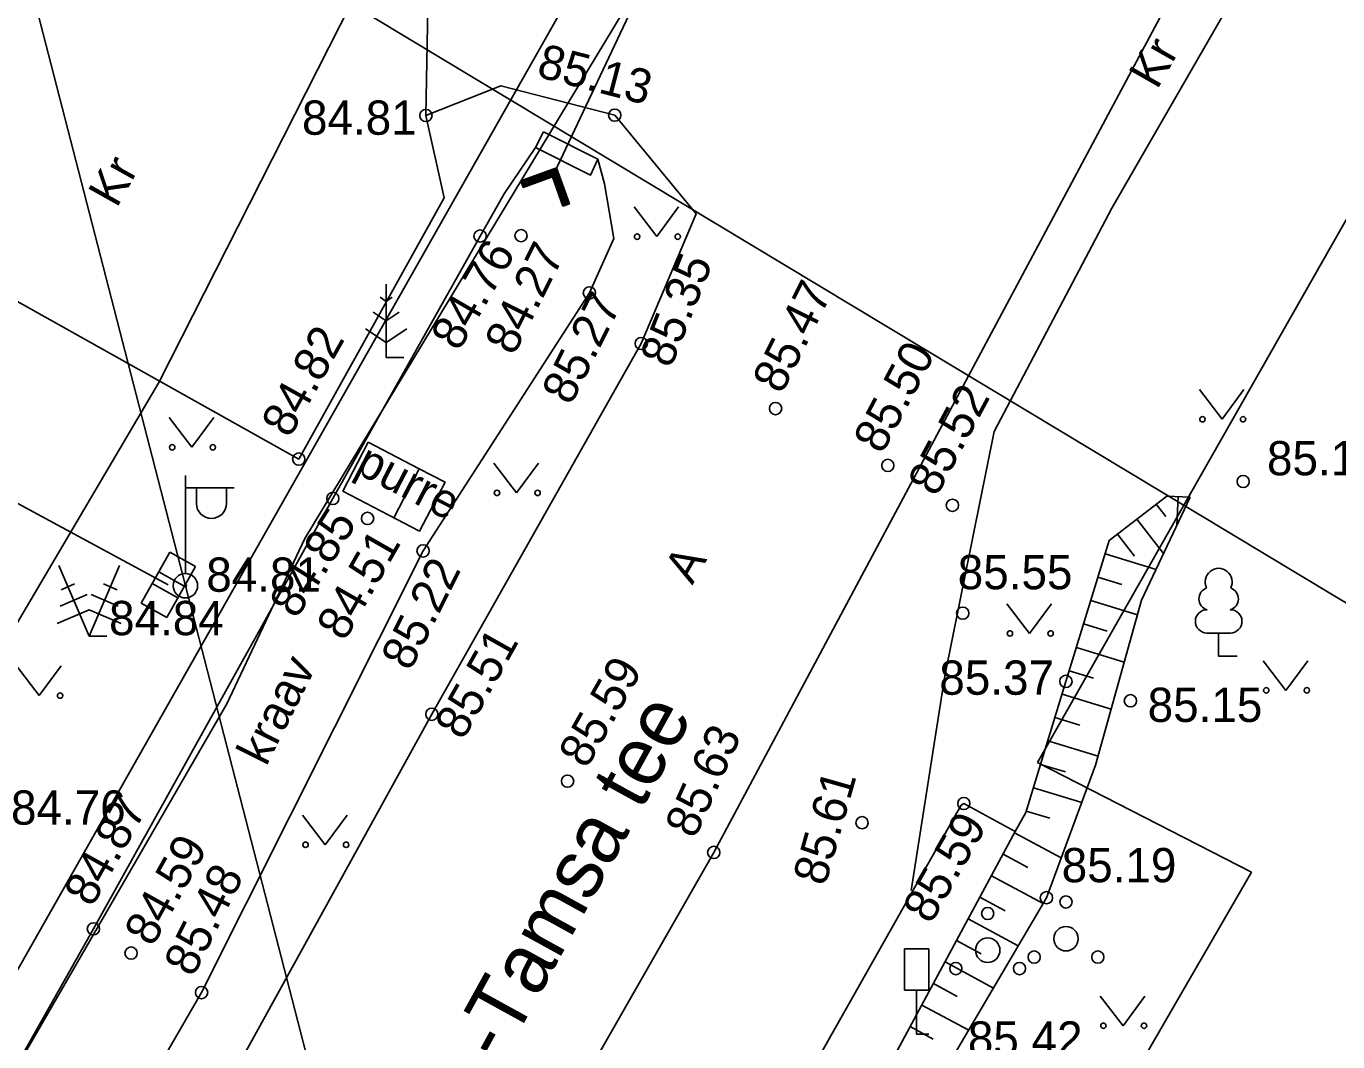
# Model space of a CAD drawing. Extents: x 648748 to 649126, y 6457789 to 6458252.
# Drawn here: x 648884.43 to 648911.21, y 6458153.1 to 6458173.84 of the extents above; entities that cross this region are included whole.
import ezdxf

# ---------------------------------------------------------------- set-up
doc = ezdxf.new("R2010")
doc.units = 0
for name, color, linetype in [('ELRAJATISMP', 7, 'Continuous'), ('HALJASTUS', 7, 'Continuous'), ('KORGUS-EH2000', 7, 'Continuous'), ('KTRASS', 7, 'Continuous'), ('LIIKLUS', 7, 'Continuous'), ('MPKAABEL', 7, 'Continuous'), ('MPOHULIIN', 7, 'Continuous'), ('PIIR', 7, 'Continuous'), ('POST', 7, 'Continuous'), ('PUU', 7, 'Continuous'), ('RAJATIS', 7, 'Continuous'), ('RELJEEF', 7, 'Continuous'), ('SITRASS', 7, 'Continuous'), ('TEE', 7, 'Continuous'), ('TRUUP', 7, 'Continuous'), ('VEEKOGU', 7, 'Continuous')]:
    doc.layers.add(name, color=color, linetype=linetype)

msp = doc.modelspace()

# ---------------------------------------------------------------- linework, layer by layer
at = {"layer": 'ELRAJATISMP'}
for p, q in [((648887.359, 6458163.099), (648886.778, 6458162.055)), ((648887.881, 6458162.809), (648887.359, 6458163.099)), ((648887.299, 6458161.765), (648887.881, 6458162.809)), ((648887.134, 6458162.696), (648887.656, 6458162.405)), ((648887.002, 6458162.459), (648887.524, 6458162.168)), ((648886.778, 6458162.055), (648887.299, 6458161.765))]:
    msp.add_line(p, q, dxfattribs=at)
at = {"layer": 'HALJASTUS'}
for p, q in [((648896.84, 6458170.152), (648897.303, 6458169.545)), ((648897.303, 6458169.545), (648897.749, 6458170.152)), ((648908.382, 6458166.42), (648908.846, 6458165.814)), ((648908.846, 6458165.814), (648909.291, 6458166.42)), ((648887.347, 6458165.847), (648887.81, 6458165.241)), ((648887.81, 6458165.241), (648888.256, 6458165.847)), ((648893.978, 6458164.916), (648894.441, 6458164.31)), ((648894.441, 6458164.31), (648894.887, 6458164.916)), ((648904.452, 6458162.044), (648904.916, 6458161.438)), ((648904.916, 6458161.438), (648905.361, 6458162.044)), ((648884.229, 6458160.775), (648884.692, 6458160.168)), ((648884.692, 6458160.168), (648885.138, 6458160.775)), ((648909.685, 6458160.882), (648910.149, 6458160.276)), ((648910.149, 6458160.276), (648910.594, 6458160.882)), ((648890.069, 6458157.727), (648890.532, 6458157.12)), ((648890.532, 6458157.12), (648890.978, 6458157.727)), ((648906.36, 6458154.031), (648906.824, 6458153.424)), ((648906.824, 6458153.424), (648907.269, 6458154.031))]:
    msp.add_line(p, q, dxfattribs=at)
for centre in [(648896.902, 6458169.545), (648897.731, 6458169.545), (648908.445, 6458165.814), (648909.274, 6458165.814), (648887.409, 6458165.241), (648888.238, 6458165.241), (648894.04, 6458164.31), (648894.869, 6458164.31), (648904.515, 6458161.438), (648905.344, 6458161.438), (648885.12, 6458160.168), (648909.748, 6458160.276), (648910.577, 6458160.276), (648890.131, 6458157.12), (648890.96, 6458157.12), (648906.423, 6458153.424), (648907.252, 6458153.424)]:
    msp.add_circle(centre, 0.055, dxfattribs=at)
at = {"layer": 'KORGUS-EH2000'}
for centre in [(648892.59, 6458172.02), (648896.444, 6458172.027), (648893.695, 6458169.558), (648894.531, 6458169.565), (648895.927, 6458168.395), (648896.987, 6458167.363), (648899.729, 6458166.032), (648889.993, 6458165.001), (648902.021, 6458164.871), (648909.277, 6458164.542), (648890.688, 6458164.197), (648903.339, 6458164.056), (648891.398, 6458163.788), (648892.53, 6458163.125), (648903.55, 6458161.853), (648905.657, 6458160.459), (648906.974, 6458160.063), (648892.71, 6458159.787), (648895.482, 6458158.42), (648903.572, 6458157.964), (648901.494, 6458157.572), (648898.467, 6458156.964), (648905.259, 6458156.04), (648885.8, 6458155.403), (648886.569, 6458154.908), (648888.008, 6458154.101)]:
    msp.add_circle(centre, 0.125, dxfattribs=at)
at = {"layer": 'KTRASS'}
msp.add_line((648918.483, 6458157.779), (648878.199, 6458182.051), dxfattribs=at)
at = {"layer": 'LIIKLUS'}
for points in [[(648902.358, 6458154.998), (648902.358, 6458154.148)], [(648902.858, 6458154.998), (648902.358, 6458154.998)], [(648902.858, 6458154.998), (648902.858, 6458154.148)], [(648902.858, 6458154.148), (648902.358, 6458154.148)], [(648902.608, 6458154.148), (648902.608, 6458153.248)], [(648902.858, 6458153.248), (648902.608, 6458153.248)]]:
    msp.add_lwpolyline(points, dxfattribs=at)
at = {"layer": 'MPKAABEL'}
msp.add_line((648877.501, 6458167.744), (648887.329, 6458162.432), dxfattribs=at)
at = {"layer": 'MPOHULIIN'}
msp.add_lwpolyline([(648879.733, 6458193.241), (648887.677, 6458162.414), (648896.676, 6458127.492), (648901.112, 6458110.279), (648910.288, 6458074.678)], dxfattribs=at)
at = {"layer": 'PIIR'}
for p, q in [((648904.5, 6458190.31), (648875.65, 6458139.39)), ((648905.08, 6458158.8), (648911.52, 6458170.14)), ((648909.45, 6458156.56), (648905.08, 6458158.8)), ((648892.07, 6458126.56), (648909.45, 6458156.56))]:
    msp.add_line(p, q, dxfattribs=at)
at = {"layer": 'POST'}
for p, q in [((648887.677, 6458162.664), (648887.677, 6458164.664)), ((648887.677, 6458164.414), (648888.677, 6458164.414)), ((648887.903, 6458164.093), (648887.903, 6458164.414)), ((648888.516, 6458164.093), (648888.516, 6458164.414))]:
    msp.add_line(p, q, dxfattribs=at)
for radius in [0.25, 0.0234]:
    msp.add_circle((648887.677, 6458162.414), radius, dxfattribs=at)
msp.add_arc((648888.21, 6458164.093), 0.306, 180, 0, dxfattribs=at)
at = {"layer": 'PUU'}
for p, q in [((648891.777, 6458168.573), (648891.777, 6458167.073)), ((648891.777, 6458168.223), (648891.653, 6458168.306)), ((648891.902, 6458168.306), (648891.777, 6458168.223)), ((648891.777, 6458167.823), (648891.511, 6458168.001)), ((648892.044, 6458168.001), (648891.777, 6458167.823)), ((648891.353, 6458167.663), (648891.777, 6458167.38)), ((648891.777, 6458167.38), (648892.202, 6458167.663)), ((648892.137, 6458167.073), (648891.777, 6458167.073)), ((648885.712, 6458161.38), (648885.091, 6458162.827)), ((648885.712, 6458161.38), (648886.333, 6458162.827)), ((648885.673, 6458162.234), (648885.121, 6458161.997)), ((648885.416, 6458162.45), (648885.141, 6458162.332)), ((648885.752, 6458162.234), (648886.303, 6458161.997)), ((648886.008, 6458162.45), (648886.284, 6458162.332)), ((648885.712, 6458161.924), (648885.056, 6458161.643)), ((648885.712, 6458161.924), (648886.369, 6458161.643)), ((648909.016, 6458161.447), (648908.536, 6458161.447)), ((648908.776, 6458160.973), (648908.776, 6458161.447)), ((648886.072, 6458161.38), (648885.712, 6458161.38)), ((648909.156, 6458160.973), (648908.776, 6458160.973))]:
    msp.add_line(p, q, dxfattribs=at)
for centre, radius in [((648905.659, 6458155.952), 0.125), ((648904.06, 6458155.717), 0.125), ((648905.659, 6458155.202), 0.25), ((648904.06, 6458154.967), 0.25), ((648905.009, 6458154.827), 0.125), ((648906.309, 6458154.827), 0.125), ((648903.41, 6458154.592), 0.125), ((648904.71, 6458154.592), 0.125)]:
    msp.add_circle(centre, radius, dxfattribs=at)
for centre, radius, start, end in [((648908.776, 6458162.492), 0.277, 332.58, 207.42), ((648908.606, 6458162.145), 0.233, 109.022, 253.142), ((648908.946, 6458162.145), 0.233, 286.851, 70.986), ((648908.539, 6458161.685), 0.238, 90.002, 269.395), ((648909.014, 6458161.685), 0.238, 270.605, 89.998)]:
    msp.add_arc(centre, radius, start, end, dxfattribs=at)
at = {"layer": 'RAJATIS'}
msp.add_line((648892.454, 6458164.8), (648891.936, 6458163.802), dxfattribs=at)
msp.add_lwpolyline([(648891.408, 6458165.344), (648892.454, 6458164.8), (648892.979, 6458164.528), (648892.46, 6458163.53), (648890.89, 6458164.346), (648891.408, 6458165.344)], dxfattribs=at)
at = {"layer": 'RELJEEF'}
for p, q in [((648907.924, 6458163.646), (648907.947, 6458164.235)), ((648907.697, 6458163.829), (648907.503, 6458164.081)), ((648907.651, 6458163.07), (648907.107, 6458163.775)), ((648907.061, 6458163.016), (648906.711, 6458163.47)), ((648907.499, 6458162.747), (648906.457, 6458163.066)), ((648906.797, 6458162.439), (648906.311, 6458162.588)), ((648907.118, 6458161.817), (648906.164, 6458162.11)), ((648906.501, 6458161.484), (648906.017, 6458161.632)), ((648906.85, 6458160.854), (648905.871, 6458161.154)), ((648906.22, 6458160.524), (648905.724, 6458160.676)), ((648906.583, 6458159.892), (648905.578, 6458160.198)), ((648905.941, 6458159.565), (648905.432, 6458159.72)), ((648906.315, 6458158.928), (648905.286, 6458159.241)), ((648905.648, 6458158.608), (648905.141, 6458158.763)), ((648905.982, 6458157.984), (648904.995, 6458158.285)), ((648905.328, 6458157.661), (648904.849, 6458157.806)), ((648905.562, 6458156.856), (648904.61, 6458157.368)), ((648904.88, 6458156.655), (648904.373, 6458156.928)), ((648905.19, 6458155.921), (648904.136, 6458156.487)), ((648904.418, 6458155.768), (648903.9, 6458156.047)), ((648904.684, 6458155.057), (648903.663, 6458155.607)), ((648903.928, 6458154.896), (648903.426, 6458155.167)), ((648904.178, 6458154.194), (648903.189, 6458154.726)), ((648903.438, 6458154.024), (648902.952, 6458154.286)), ((648903.672, 6458153.331), (648902.715, 6458153.846)), ((648902.949, 6458153.152), (648902.478, 6458153.405))]:
    msp.add_line(p, q, dxfattribs=at)
for points in [[(648895.718, 6458141.704), (648896.98, 6458142.131), (648898.022, 6458143.684), (648898.915, 6458143.306), (648901.478, 6458142.068), (648902.049, 6458142.102), (648905.09, 6458148.216), (648905.916, 6458150.124), (648905.534, 6458150.948), (648903.317, 6458152.725), (648905.259, 6458156.04), (648906.264, 6458158.745), (648907.202, 6458162.117), (648908.197, 6458164.225)], [(648908.197, 6458164.225), (648907.715, 6458164.244), (648906.541, 6458163.339), (648905.657, 6458160.459), (648904.841, 6458157.779), (648904.623, 6458157.392)]]:
    msp.add_lwpolyline(points, dxfattribs=at)
at = {"layer": 'SITRASS'}
for points in [[(648929.925, 6458240.085), (648929.233, 6458238.833), (648926.729, 6458233.327), (648923.21, 6458225.506), (648918.966, 6458215.361), (648917.027, 6458210.342), (648911.341, 6458199.533), (648902.157, 6458183.584), (648896.992, 6458174.764), (648890.118, 6458163.377), (648888.523, 6458160), (648880.878, 6458146.779), (648876.372, 6458138.998), (648873.186, 6458136.533), (648872.398, 6458135.159), (648870.194, 6458131.921), (648868.778, 6458129.583), (648863.975, 6458121.708)], [(648896.343, 6458186.017), (648897.439, 6458185.494), (648891.994, 6458176.157), (648887.134, 6458166.562), (648880.865, 6458155.928), (648874.577, 6458143.726), (648870.442, 6458134.893), (648860.973, 6458120.207), (648854.483, 6458107.787), (648851.762, 6458098.853), (648850.917, 6458095.378), (648847.878, 6458090.581), (648844.467, 6458087.013), (648842.522, 6458085.072), (648840.521, 6458082.239)]]:
    msp.add_lwpolyline(points, dxfattribs=at)
at = {"layer": 'TEE'}
msp.add_line((648892.59, 6458172.02), (648892.961, 6458170.34), dxfattribs=at)
for points in [[(648891.319, 6458123.494), (648901.175, 6458127.077), (648933.887, 6458139.607), (648944.575, 6458143.741), (648947.822, 6458145.717), (648948.882, 6458147.636), (648949.478, 6458151.73), (648949.531, 6458156.617), (648950.372, 6458161.859), (648951.909, 6458167.68), (648954.505, 6458172.94), (648956.528, 6458180.218), (648952.525, 6458185.448), (648945.526, 6458192.898), (648938.29, 6458202.321), (648932.248, 6458208.399), (648929.676, 6458210.569), (648928.257, 6458209.969), (648926.047, 6458207.531), (648924.786, 6458206.368), (648922.091, 6458200.973), (648909.112, 6458176.906), (648898.467, 6458156.964), (648883.402, 6458130.595)], [(648902.496, 6458156.185), (648903.183, 6458160.572), (648904.191, 6458165.567), (648906.598, 6458170.127), (648910.322, 6458176.61), (648916.438, 6458188.99), (648922.963, 6458200.444), (648925.76, 6458205.755), (648928.587, 6458207.759), (648932.657, 6458207.561), (648933.376, 6458207.264)], [(648910.613, 6458192.21), (648903.667, 6458179.751), (648902.811, 6458178.379), (648900.807, 6458174.931), (648897.151, 6458176.001), (648894.164, 6458177.881), (648892.628, 6458174.223), (648892.59, 6458172.02), (648894.122, 6458172.629), (648896.444, 6458172.027), (648898.105, 6458170.013), (648896.987, 6458167.363), (648892.71, 6458159.787), (648886.897, 6458149.241), (648880.501, 6458138.274)], [(648892.961, 6458170.34), (648889.993, 6458165.001), (648880.68, 6458170.217), (648879.296, 6458170.992)], [(648894.686, 6458142.224), (648895.718, 6458141.704), (648900.554, 6458149.829), (648904.623, 6458157.392), (648903.572, 6458157.964), (648903.52, 6458157.93)], [(648903.52, 6458157.93), (648899.284, 6458150.429), (648894.686, 6458142.224)]]:
    msp.add_lwpolyline(points, dxfattribs=at)
at = {"layer": 'TRUUP'}
for p, q in [((648898.615, 6458178.065), (648895.215, 6458170.857)), ((648895.258, 6458170.948), (648894.526, 6458170.685)), ((648895.215, 6458170.857), (648894.55, 6458170.618)), ((648894.816, 6458170.638), (648894.836, 6458170.796)), ((648894.842, 6458170.647), (648894.862, 6458170.806)), ((648894.869, 6458170.657), (648894.888, 6458170.815)), ((648894.895, 6458170.666), (648894.915, 6458170.824)), ((648894.922, 6458170.676), (648894.941, 6458170.834)), ((648894.948, 6458170.685), (648894.967, 6458170.843)), ((648894.974, 6458170.695), (648894.994, 6458170.853)), ((648895.001, 6458170.704), (648895.02, 6458170.862)), ((648895.027, 6458170.713), (648895.047, 6458170.872)), ((648895.053, 6458170.723), (648895.073, 6458170.881)), ((648895.08, 6458170.732), (648895.099, 6458170.891)), ((648895.106, 6458170.742), (648895.125, 6458170.9)), ((648895.133, 6458170.752), (648895.152, 6458170.909)), ((648895.159, 6458170.761), (648895.178, 6458170.919)), ((648895.182, 6458170.741), (648895.205, 6458170.929)), ((648895.2, 6458170.688), (648895.231, 6458170.938)), ((648895.454, 6458170.191), (648895.215, 6458170.857)), ((648895.219, 6458170.636), (648895.257, 6458170.948)), ((648895.238, 6458170.584), (648895.276, 6458170.898)), ((648895.256, 6458170.531), (648895.295, 6458170.845)), ((648895.522, 6458170.215), (648895.258, 6458170.948)), ((648895.276, 6458170.479), (648895.314, 6458170.793)), ((648894.574, 6458170.551), (648894.526, 6458170.685)), ((648894.54, 6458170.645), (648894.546, 6458170.692)), ((648894.559, 6458170.593), (648894.572, 6458170.701)), ((648895.173, 6458170.766), (648894.574, 6458170.551)), ((648894.579, 6458170.553), (648894.599, 6458170.711)), ((648894.606, 6458170.562), (648894.625, 6458170.721)), ((648894.632, 6458170.571), (648894.651, 6458170.73)), ((648894.658, 6458170.581), (648894.677, 6458170.74)), ((648894.685, 6458170.591), (648894.704, 6458170.749)), ((648894.711, 6458170.6), (648894.731, 6458170.758)), ((648894.737, 6458170.61), (648894.757, 6458170.768)), ((648894.764, 6458170.619), (648894.783, 6458170.777)), ((648894.79, 6458170.629), (648894.809, 6458170.787)), ((648895.387, 6458170.167), (648895.173, 6458170.766)), ((648895.294, 6458170.427), (648895.333, 6458170.741)), ((648895.313, 6458170.375), (648895.352, 6458170.689)), ((648895.331, 6458170.322), (648895.37, 6458170.636)), ((648895.351, 6458170.27), (648895.389, 6458170.584)), ((648895.369, 6458170.218), (648895.408, 6458170.532)), ((648895.388, 6458170.168), (648895.426, 6458170.479)), ((648895.414, 6458170.177), (648895.446, 6458170.427)), ((648895.441, 6458170.187), (648895.464, 6458170.375)), ((648895.468, 6458170.196), (648895.483, 6458170.323)), ((648895.494, 6458170.205), (648895.502, 6458170.27)), ((648895.387, 6458170.167), (648895.522, 6458170.215))]:
    msp.add_line(p, q, dxfattribs=at)
msp.add_lwpolyline([(648894.989, 6458171.687), (648896.101, 6458171.13), (648895.953, 6458170.803), (648894.824, 6458171.369), (648894.989, 6458171.687)], dxfattribs=at)
at = {"layer": 'VEEKOGU'}
msp.add_lwpolyline([(648894.824, 6458171.369), (648894.188, 6458170.423), (648893.695, 6458169.558), (648890.688, 6458164.197), (648885.8, 6458155.403), (648881.852, 6458148.408), (648881.551, 6458147.775), (648882.109, 6458147.118), (648882.61, 6458146.464), (648883.683, 6458146.633), (648888.008, 6458154.101), (648892.53, 6458163.125), (648895.927, 6458168.395), (648896.425, 6458169.506), (648896.234, 6458170.624), (648896.101, 6458171.13)], dxfattribs=at)

# ---------------------------------------------------------------- texts
at = {"layer": 'KORGUS-EH2000'}
for s, rotation, p in [('85.13', 345.4816, (648894.826, 6458172.82)), ('84.76', 59.9558, (648893.259, 6458167.181)), ('84.27', 63.3112, (648894.383, 6458167.093)), ('85.35', 68.3177, (648897.589, 6458166.836)), ('85.47', 63.5662, (648899.854, 6458166.308)), ('85.27', 63.3407, (648895.548, 6458166.077)), ('84.82', 60.9258, (648889.806, 6458165.409)), ('85.50', 62.0326, (648901.904, 6458165.081)), ('85.52', 61.7747, (648903.014, 6458164.208)), ('84.85', 57.6927, (648889.944, 6458161.714)), ('84.51', 60.2282, (648890.928, 6458161.256)), ('85.22', 63.4349, (648892.268, 6458160.648)), ('85.51', 60.5551, (648893.346, 6458159.235)), ('85.59', 60.5551, (648895.872, 6458158.654)), ('85.63', 65.8001, (648898.081, 6458157.222)), ('85.61', 74.1102, (648900.743, 6458156.259)), ('84.87', 60.9356, (648885.773, 6458155.824)), ('85.59', 60.3215, (648902.899, 6458155.478)), ('84.59', 60.9356, (648887.007, 6458155.015)), ('85.48', 63.3854, (648887.834, 6458154.395))]:
    msp.add_text(s, height=0.7, rotation=rotation, dxfattribs=at).set_placement(p)
for s, p in [('84.81', (648890.058, 6458171.627)), ('85.14', (648909.763, 6458164.669)), ('85.55', (648903.448, 6458162.341)), ('84.81', (648888.104, 6458162.29)), ('84.84', (648886.119, 6458161.403)), ('85.37', (648903.072, 6458160.186)), ('85.15', (648907.326, 6458159.63)), ('84.76', (648884.116, 6458157.531)), ('85.19', (648905.571, 6458156.355)), ('85.42', (648903.655, 6458152.813))]:
    msp.add_text(s, height=0.7, dxfattribs=at).set_placement(p)
at = {"layer": 'RAJATIS'}
msp.add_text('purre', height=0.7, rotation=332.5487, dxfattribs=at).set_placement((648891.113, 6458164.739))
at = {"layer": 'TEE'}
for s, height, rotation, p in [('Kr', 0.7, 60.3302, (648907.519, 6458172.532)), ('Kr', 0.7, 60.6422, (648886.274, 6458170.113)), ('A', 0.7, 60.2687, (648898.029, 6458162.414)), ('Nõo-Tamsa tee', 1.2, 61.136, (648892.714, 6458150.069))]:
    msp.add_text(s, height=height, rotation=rotation, dxfattribs=at).set_placement(p)
at = {"layer": 'VEEKOGU'}
msp.add_text('kraav', height=0.7, rotation=63.3854, dxfattribs=at).set_placement((648889.327, 6458158.704))

doc.saveas('drawing.dxf')
